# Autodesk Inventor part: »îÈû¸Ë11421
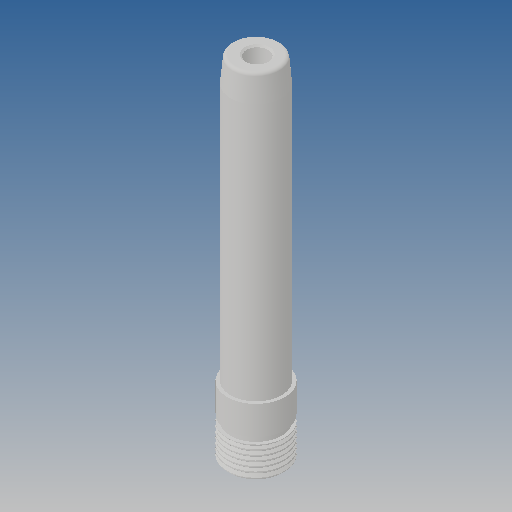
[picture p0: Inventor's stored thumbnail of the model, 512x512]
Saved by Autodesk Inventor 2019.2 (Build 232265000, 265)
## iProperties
Created: 2013-09
Part Number: »îÈû¸Ë11421
Material: Ogólny
Document SubType Name: Modeling
Designer: CADENGINEERING4
Density: 1 g/cm^3
Appearance: Domyślna
Author: CADENGINEERING4
Revision Number: ÈÎºÎ
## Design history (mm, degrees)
feature "µ¹½Ç3"
node "Bryła1"
